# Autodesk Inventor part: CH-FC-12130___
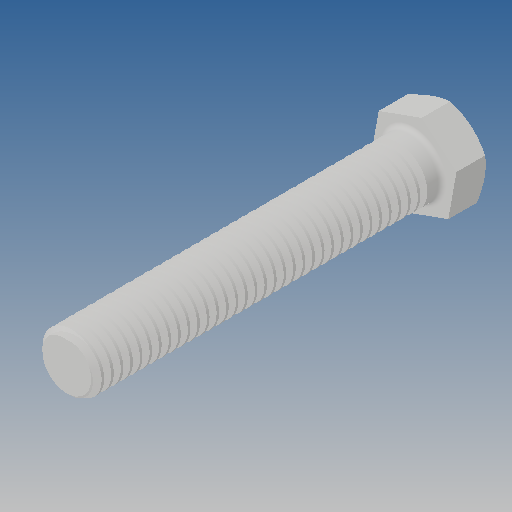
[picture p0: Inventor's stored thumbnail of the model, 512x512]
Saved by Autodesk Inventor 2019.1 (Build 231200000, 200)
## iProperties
Created: 2012-09
Part Number: CH-FC-12130___
Material: Ogólny
Document SubType Name: Modeling
Designer: CADENGINEERING4
Density: 1 g/cm^3
Appearance: Domyślna
Author: CADENGINEERING4
Revision Number: ÈÎºÎ
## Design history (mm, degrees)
feature "NONE"
node "Bryła1"
